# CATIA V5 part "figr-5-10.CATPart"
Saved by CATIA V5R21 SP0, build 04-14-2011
Part number: Part1
Bounding box of the stored display mesh (mm): x 0 to 150, y -70 to 70, z -150 to 69.804
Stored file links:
  D:\CATIA V5R21 E-RESOURCES\CATIA-V5R21\catia-v5r21-prt\c05-catia-v5r20-prt\catia-v5r21-figr-5-10.CATPart
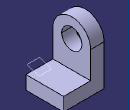
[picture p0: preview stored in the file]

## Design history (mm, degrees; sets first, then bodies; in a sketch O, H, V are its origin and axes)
Set1
  Plane1: type 2Lines, Element1 edge of Pad2, Element2 edge of Pad2
Body1 (main body)
  Sketch1 on yz-plane, origin (0, 0, 0), H (0, 1, 0), V (0, 0, 1)
    arc A1 centre (0, 0) radius 70 from (70, 0) to (-70, 0) ccw
    point P1 (70, 0)
    point P2 (-70, 0)
    line L1 (-70, 0) -> (-70, -150)
    line L2 (-70, -150) -> (70, -150)
    line L3 (70, -150) -> (70, 0)
    circle A2 centre (0, 0) radius 37.5
    radius A1 = 70
    radius A2 = 37.5
    distance O L2 = 150
    coincidence: P1 H, P2 H
    tangency: L1 A1, L3 A1
    horizontal: L2 H
  Pad1: profile Sketch1, direction (1, 0, 0), length 50
  Sketch2 on face of Pad1, origin (50, 0, 0), H (0, 1, 0), V (0, 0, 1)
    line L1 (-70, -150) -> (70, -150)
    line L2 (70, -150) -> (70, -100)
    line L3 (70, -100) -> (-70, -100)
    line L4 (-70, -100) -> (-70, -150)
    reference projected line E1 (-70, -150) -> (70, -150) from edge [face of Pad1 | face of Pad1]
    reference projected line E2 (-70, 0) -> (-70, -150) from edge [face of Pad1 | face of Pad1]
    reference projected line E3 (70, -150) -> (70, 0) from edge [face of Pad1 | face of Pad1]
    length L2 = 50
    horizontal: L1 H, L3 H
    vertical: L2 V, L4 V
    coincidence: L1 E1, E2 L4, L2 E3
  Pad2: profile Sketch2, direction (1, 0, 0), length 100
